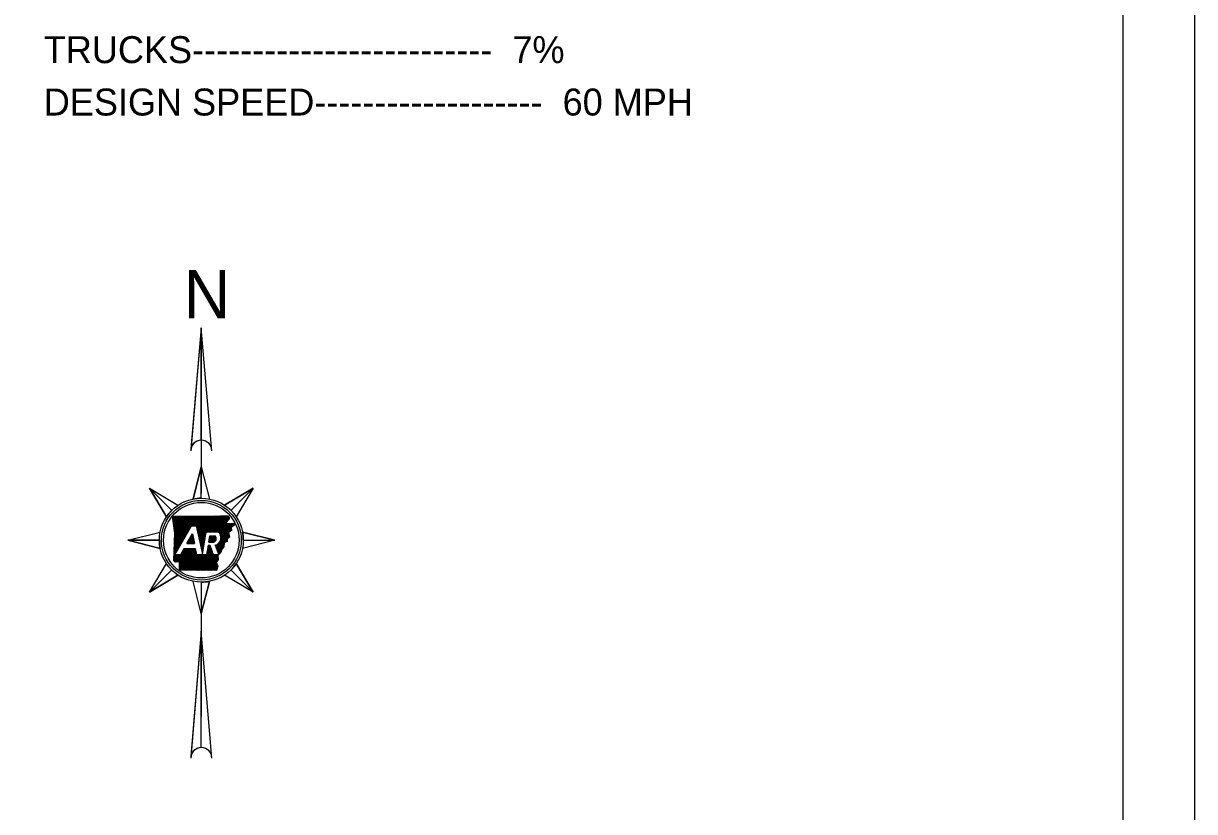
# Model space of a CAD drawing. Extents: x 646058 to 725608, y 1473014 to 1561048.
# Drawn here: x 700985 to 717726, y 1526523 to 1537793 of the extents above; entities that cross this region are included whole.
import ezdxf

# ---------------------------------------------------------------- set-up
doc = ezdxf.new("R2010")
doc.units = 0
for name, color, linetype in [('R_Border Notes', 7, 'Continuous'), ('R_Grid', 7, 'Continuous'), ('R_MOT', 7, 'Continuous'), ('T_Vehicle Path Rt', 7, 'Continuous')]:
    doc.layers.add(name, color=color, linetype=linetype)

msp = doc.modelspace()

# ---------------------------------------------------------------- linework, layer by layer
at = {"layer": 'R_Border Notes'}
msp.add_line((716704, 1516037), (716704, 1560211), dxfattribs=at)
at = {"layer": 'R_Grid'}
for p, q in [((703528, 1533438), (703380, 1531708)), ((703528, 1533438), (703528, 1531069)), ((703528, 1531833), (703528, 1533438)), ((703382, 1531732), (703389, 1531739)), ((703383, 1531741), (703397, 1531755)), ((703528, 1531453), (703411, 1530992)), ((703528, 1531003), (703528, 1531453)), ((702785, 1531146), (703104, 1530828)), ((703104, 1530828), (702785, 1531146)), ((702785, 1531146), (703029, 1530737)), ((704270, 1531146), (703861, 1530902)), ((703952, 1530828), (704270, 1531146)), ((703952, 1530828), (704270, 1531146)), ((703149, 1530193), (703386, 1530611)), ((703323, 1530357), (703400, 1530494)), ((703386, 1530611), (703456, 1530611)), ((703599, 1530524), (703763, 1530524)), ((703650, 1530465), (703727, 1530465)), ((704578, 1530403), (704116, 1530520)), ((702478, 1530403), (702928, 1530403)), ((702928, 1530403), (702478, 1530403)), ((702478, 1530403), (702939, 1530286)), ((703323, 1530357), (703430, 1530357)), ((703654, 1530326), (703626, 1530326)), ((703634, 1530376), (703705, 1530376)), ((703703, 1530193), (703654, 1530326)), ((703724, 1530333), (703776, 1530193)), ((704128, 1530403), (704578, 1530403)), ((704128, 1530403), (704578, 1530403)), ((703230, 1530193), (703149, 1530193)), ((703280, 1530281), (703230, 1530193)), ((703446, 1530281), (703280, 1530281)), ((703603, 1530193), (703465, 1530193)), ((703776, 1530193), (703703, 1530193)), ((702785, 1529661), (703104, 1529979)), ((703104, 1529979), (702785, 1529661)), ((703952, 1529979), (704270, 1529661)), ((703952, 1529979), (704270, 1529661)), ((704270, 1529661), (704027, 1530070)), ((702785, 1529661), (703194, 1529905)), ((703528, 1529353), (703645, 1529815)), ((703528, 1529803), (703528, 1529803)), ((703528, 1529803), (703528, 1527883)), ((703528, 1529803), (703528, 1529353)), ((703528, 1529103), (703380, 1527312)), ((703528, 1527438), (703528, 1529103))]:
    msp.add_line(p, q, dxfattribs=at)
for points in [[(703678, 1531683), (703528, 1533438), (703378, 1531683)], [(703411, 1530992), (703528, 1531453), (703645, 1530992)], [(703029, 1530737), (702785, 1531146), (703194, 1530902)], [(703861, 1530902), (704270, 1531146), (704027, 1530737)], [(703118, 1530747), (703352, 1530747), (703558, 1530747), (703800, 1530751), (703912, 1530753)], [(703135, 1530113), (703148, 1530506), (703118, 1530747)], [(703986, 1530646), (704006, 1530625), (703956, 1530583), (703961, 1530541), (703918, 1530513), (703933, 1530448), (703899, 1530418), (703896, 1530385), (703856, 1530370), (703849, 1530308), (703820, 1530276), (703806, 1530229), (703764, 1530190), (703767, 1530122), (703738, 1530089), (703764, 1530030), (703746, 1529972)], [(703878, 1530640), (703988, 1530646)], [(702939, 1530286), (702478, 1530403), (702939, 1530520)], [(703400, 1530494), (703430, 1530357)], [(703456, 1530611), (703543, 1530204), (703599, 1530524)], [(703634, 1530376), (703650, 1530465)], [(704116, 1530520), (704578, 1530403), (704116, 1530286)], [(703626, 1530326), (703603, 1530193)], [(703465, 1530193), (703446, 1530281)], [(703194, 1529905), (702785, 1529661), (703029, 1530070)], [(703746, 1529972), (703215, 1529973), (703215, 1530090)], [(704027, 1530070), (704270, 1529661), (703861, 1529905)], [(703645, 1529815), (703528, 1529353), (703411, 1529815)], [(703678, 1527288), (703528, 1529103), (703378, 1527288)]]:
    msp.add_lwpolyline(points, dxfattribs=at)
for radius in [600, 540]:
    msp.add_circle((703528, 1530403), radius, dxfattribs=at)
for centre, radius, start, end in [((703528, 1531683), 150, 360, 180), ((703528, 1531683), 150, 90, 170.2296), ((703528, 1530403), 600, 90, 101.2291), ((703528, 1530403), 600, 135, 146.2291), ((703528, 1530403), 600, 45, 56.2291), ((703688, 1530427), 54.3, 288.1268, 43.8902), ((703702, 1530437), 106, 281.8626, 54.8705), ((703528, 1530403), 600, 360, 11.2291), ((703528, 1530403), 600, 180, 191.2291), ((703528, 1530403), 600, 225, 236.2291), ((703528, 1530403), 600, 315, 326.2291), ((703528, 1530403), 600, 270, 281.2291), ((703528, 1527288), 150, 360, 180), ((703528, 1527288), 150, 90, 170.5511)]:
    msp.add_arc(centre, radius, start, end, dxfattribs=at)
for points in [[(703912, 1530753), (703913, 1530747), (703915, 1530744), (703916, 1530738), (703918, 1530735), (703922, 1530732), (703926, 1530728), (703927, 1530723), (703926, 1530718), (703925, 1530713), (703925, 1530708), (703924, 1530703), (703920, 1530700), (703917, 1530697), (703914, 1530694), (703912, 1530691), (703908, 1530687), (703904, 1530684), (703901, 1530680), (703898, 1530676), (703897, 1530672), (703894, 1530669), (703891, 1530666), (703887, 1530662), (703886, 1530658), (703882, 1530654), (703882, 1530649), (703879, 1530646), (703879, 1530645)], [(703215, 1530090), (703216, 1530090), (703213, 1530092), (703209, 1530093), (703205, 1530094), (703200, 1530094), (703195, 1530095), (703191, 1530098), (703186, 1530095), (703180, 1530092), (703177, 1530095), (703173, 1530093), (703170, 1530094), (703165, 1530091), (703160, 1530092), (703157, 1530091), (703152, 1530091), (703151, 1530096), (703147, 1530097), (703144, 1530099), (703141, 1530104), (703139, 1530108), (703135, 1530113)]]:
    msp.add_spline(points, degree=3, dxfattribs=at)
at = {"layer": 'R_MOT'}
for p, q in [((703119, 1530741), (703124, 1530747)), ((703121, 1530726), (703141, 1530747)), ((703123, 1530711), (703158, 1530747)), ((703124, 1530696), (703175, 1530747)), ((703126, 1530681), (703192, 1530747)), ((703128, 1530666), (703209, 1530747)), ((703130, 1530651), (703226, 1530747)), ((703132, 1530636), (703243, 1530747)), ((703134, 1530621), (703260, 1530747)), ((703136, 1530606), (703277, 1530747)), ((703138, 1530591), (703294, 1530747)), ((703140, 1530575), (703311, 1530747)), ((703141, 1530560), (703328, 1530747)), ((703143, 1530545), (703345, 1530747)), ((703144, 1530376), (703515, 1530747)), ((703144, 1530394), (703498, 1530747)), ((703145, 1530411), (703481, 1530747)), ((703145, 1530530), (703362, 1530747)), ((703146, 1530429), (703464, 1530747)), ((703146, 1530446), (703447, 1530747)), ((703147, 1530464), (703430, 1530747)), ((703147, 1530481), (703413, 1530747)), ((703147, 1530515), (703379, 1530747)), ((703148, 1530499), (703396, 1530747)), ((703396, 1530611), (703532, 1530747)), ((703413, 1530611), (703549, 1530747)), ((703430, 1530611), (703566, 1530747)), ((703447, 1530611), (703583, 1530747)), ((703457, 1530605), (703600, 1530748)), ((703460, 1530591), (703617, 1530748)), ((703463, 1530577), (703635, 1530748)), ((703466, 1530563), (703652, 1530749)), ((703469, 1530549), (703669, 1530749)), ((703472, 1530535), (703686, 1530749)), ((703475, 1530521), (703704, 1530749)), ((703478, 1530507), (703721, 1530750)), ((703481, 1530493), (703738, 1530750)), ((703484, 1530479), (703755, 1530750)), ((703487, 1530465), (703773, 1530750)), ((703490, 1530451), (703790, 1530751)), ((703493, 1530437), (703807, 1530751)), ((703496, 1530423), (703825, 1530751)), ((703614, 1530524), (703842, 1530752)), ((703631, 1530524), (703859, 1530752)), ((703648, 1530524), (703877, 1530753)), ((703665, 1530524), (703894, 1530753)), ((703682, 1530524), (703911, 1530753)), ((703699, 1530524), (703915, 1530740)), ((703716, 1530524), (703923, 1530731)), ((703733, 1530524), (703926, 1530717)), ((703750, 1530524), (703887, 1530661)), ((703765, 1530522), (703884, 1530641)), ((703775, 1530515), (703901, 1530642)), ((703783, 1530506), (703919, 1530642)), ((703790, 1530496), (703937, 1530643)), ((703796, 1530486), (703955, 1530644)), ((703802, 1530474), (703973, 1530645)), ((703806, 1530461), (703989, 1530644)), ((703808, 1530446), (703997, 1530635)), ((703142, 1530323), (703328, 1530509)), ((703142, 1530306), (703306, 1530470)), ((703143, 1530359), (703372, 1530588)), ((703143, 1530341), (703350, 1530548)), ((703366, 1530434), (703405, 1530472)), ((703388, 1530473), (703402, 1530486)), ((703499, 1530409), (703596, 1530505)), ((703502, 1530395), (703592, 1530485)), ((703505, 1530381), (703588, 1530464)), ((703635, 1530376), (703724, 1530465)), ((703638, 1530396), (703707, 1530465)), ((703642, 1530417), (703690, 1530465)), ((703645, 1530437), (703673, 1530465)), ((703649, 1530458), (703656, 1530465)), ((703734, 1530305), (703922, 1530493)), ((703739, 1530292), (703926, 1530479)), ((703743, 1530280), (703929, 1530465)), ((703790, 1530377), (703919, 1530507)), ((703804, 1530409), (703958, 1530563)), ((703808, 1530429), (703956, 1530578)), ((703939, 1530527), (703960, 1530548)), ((703989, 1530611), (704005, 1530626)), ((703139, 1530236), (703217, 1530314)), ((703140, 1530271), (703261, 1530392)), ((703140, 1530253), (703239, 1530353)), ((703141, 1530288), (703284, 1530431)), ((703324, 1530357), (703411, 1530444)), ((703341, 1530357), (703414, 1530430)), ((703344, 1530394), (703408, 1530458)), ((703358, 1530357), (703417, 1530416)), ((703375, 1530357), (703420, 1530402)), ((703392, 1530357), (703423, 1530389)), ((703409, 1530357), (703426, 1530375)), ((703426, 1530357), (703429, 1530361)), ((703508, 1530367), (703585, 1530444)), ((703511, 1530353), (703581, 1530423)), ((703514, 1530339), (703578, 1530403)), ((703517, 1530325), (703574, 1530382)), ((703520, 1530311), (703570, 1530362)), ((703523, 1530297), (703567, 1530341)), ((703526, 1530283), (703563, 1530320)), ((703529, 1530269), (703560, 1530300)), ((703613, 1530251), (703663, 1530302)), ((703616, 1530272), (703659, 1530314)), ((703620, 1530292), (703654, 1530326)), ((703623, 1530313), (703637, 1530326)), ((703652, 1530376), (703733, 1530457)), ((703668, 1530376), (703739, 1530446)), ((703685, 1530376), (703742, 1530432)), ((703702, 1530376), (703741, 1530414)), ((703725, 1530330), (703730, 1530335)), ((703730, 1530317), (703762, 1530350)), ((703748, 1530268), (703932, 1530452)), ((703753, 1530255), (703854, 1530357)), ((703757, 1530243), (703853, 1530338)), ((703762, 1530230), (703851, 1530319)), ((703874, 1530377), (703898, 1530400)), ((703135, 1530113), (703215, 1530193)), ((703136, 1530130), (703198, 1530193)), ((703136, 1530148), (703181, 1530193)), ((703137, 1530183), (703151, 1530196)), ((703137, 1530166), (703164, 1530193)), ((703138, 1530201), (703173, 1530235)), ((703139, 1530218), (703195, 1530275)), ((703142, 1530102), (703320, 1530281)), ((703152, 1530096), (703337, 1530281)), ((703164, 1530091), (703354, 1530281)), ((703184, 1530094), (703371, 1530281)), ((703201, 1530094), (703388, 1530281)), ((703215, 1530057), (703439, 1530281)), ((703215, 1530074), (703422, 1530281)), ((703215, 1530091), (703405, 1530281)), ((703215, 1530040), (703448, 1530273)), ((703215, 1530023), (703451, 1530259)), ((703215, 1530006), (703454, 1530245)), ((703215, 1529990), (703457, 1530231)), ((703216, 1529973), (703460, 1530217)), ((703233, 1529973), (703463, 1530203)), ((703249, 1530227), (703303, 1530281)), ((703250, 1529973), (703470, 1530193)), ((703267, 1529973), (703487, 1530193)), ((703272, 1530266), (703286, 1530281)), ((703283, 1529973), (703504, 1530193)), ((703300, 1529973), (703521, 1530193)), ((703317, 1529973), (703538, 1530193)), ((703334, 1529973), (703555, 1530193)), ((703351, 1529973), (703572, 1530193)), ((703368, 1529973), (703589, 1530193)), ((703385, 1529973), (703677, 1530264)), ((703402, 1529973), (703682, 1530252)), ((703419, 1529973), (703686, 1530240)), ((703436, 1529973), (703691, 1530227)), ((703453, 1529972), (703695, 1530215)), ((703470, 1529972), (703700, 1530203)), ((703487, 1529972), (703708, 1530193)), ((703504, 1529972), (703724, 1530193)), ((703521, 1529972), (703741, 1530193)), ((703532, 1530255), (703556, 1530279)), ((703535, 1530241), (703553, 1530259)), ((703538, 1530227), (703549, 1530238)), ((703538, 1529972), (703758, 1530193)), ((703541, 1530213), (703545, 1530218)), ((703555, 1529972), (703764, 1530182)), ((703572, 1529972), (703765, 1530166)), ((703588, 1529972), (703766, 1530149)), ((703605, 1529972), (703766, 1530133)), ((703606, 1530210), (703672, 1530277)), ((703609, 1530231), (703668, 1530289)), ((703766, 1530218), (703818, 1530270)), ((703771, 1530206), (703811, 1530246)), ((703622, 1529972), (703738, 1530088)), ((703639, 1529972), (703744, 1530077)), ((703656, 1529972), (703749, 1530065)), ((703673, 1529972), (703754, 1530053)), ((703690, 1529972), (703759, 1530041)), ((703707, 1529972), (703764, 1530029)), ((703724, 1529972), (703756, 1530004)), ((703741, 1529972), (703748, 1529980))]:
    msp.add_line(p, q, dxfattribs=at)
msp.add_circle((703528, 1530403), 570, dxfattribs=at)
at = {"layer": 'T_Vehicle Path Rt'}
msp.add_lwpolyline([(646058, 1561048), (717726, 1561048), (717726, 1515181), (646058, 1515181)], close=True, dxfattribs=at)

# ---------------------------------------------------------------- texts
at = {"layer": 'R_Grid'}
for s, p in [('TRUCKS-------------------------  7%', (701276, 1537225)), ('DESIGN SPEED-------------------  60 MPH', (701276, 1536476))]:
    msp.add_text(s, height=385.55, dxfattribs=at).set_placement(p)
for s, height, p in [('N', 692, (703275, 1533574)), ('DWB 7-27-17', 11.67, (703491, 1529853))]:
    msp.add_text(s, height=height, rotation=360, dxfattribs=at).set_placement(p)

doc.saveas('drawing.dxf')
